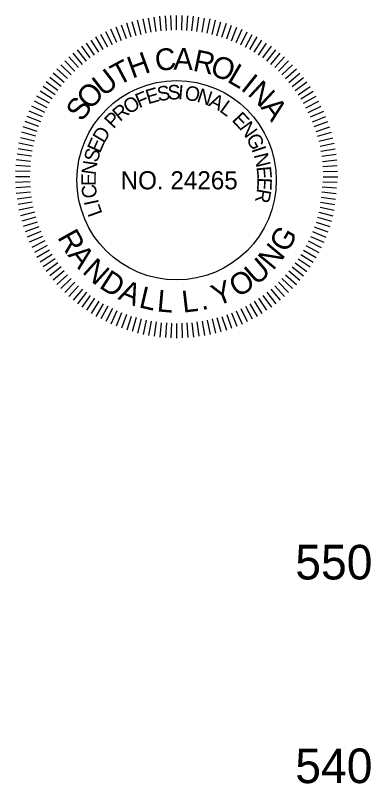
# Model space of a CAD drawing. Extents: x 1964849 to 1967422, y 1116563 to 1122210.
# Drawn here: x 1966503.4 to 1966590.7, y 1121475.5 to 1121664.1 of the extents above; entities that cross this region are included whole.
import ezdxf

# ---------------------------------------------------------------- set-up
doc = ezdxf.new("R2010")
doc.units = 0
doc.layers.add('RD_DDB_Profile_Elev', color=7, linetype='Continuous')
doc.layers.add('RD_TX_PEShield', color=7, linetype='Continuous')

msp = doc.modelspace()

# ---------------------------------------------------------------- linework, layer by layer
at = {"layer": 'RD_TX_PEShield'}
for p, q in [((1966539.21, 1121660.3), (1966538.84, 1121663.84)), ((1966539.21, 1121660.3), (1966538.84, 1121663.84)), ((1966540.47, 1121660.37), (1966540.22, 1121663.91)), ((1966540.47, 1121660.37), (1966540.22, 1121663.91)), ((1966541.72, 1121660.43), (1966541.6, 1121663.99)), ((1966541.72, 1121660.43), (1966541.6, 1121663.99)), ((1966542.98, 1121660.5), (1966542.98, 1121664.06)), ((1966542.98, 1121660.5), (1966542.98, 1121664.06)), ((1966544.24, 1121660.43), (1966544.36, 1121663.99)), ((1966544.24, 1121660.43), (1966544.36, 1121663.99)), ((1966545.49, 1121660.37), (1966545.74, 1121663.91)), ((1966545.49, 1121660.37), (1966545.74, 1121663.91)), ((1966546.75, 1121660.3), (1966547.12, 1121663.84)), ((1966546.75, 1121660.3), (1966547.12, 1121663.84)), ((1966531.84, 1121658.74), (1966530.74, 1121662.12)), ((1966531.84, 1121658.74), (1966530.74, 1121662.12)), ((1966533.06, 1121659.06), (1966532.08, 1121662.48)), ((1966533.06, 1121659.06), (1966532.08, 1121662.48)), ((1966534.27, 1121659.39), (1966533.41, 1121662.84)), ((1966534.27, 1121659.39), (1966533.41, 1121662.84)), ((1966535.49, 1121659.71), (1966534.75, 1121663.19)), ((1966535.49, 1121659.71), (1966534.75, 1121663.19)), ((1966536.73, 1121659.91), (1966536.11, 1121663.41)), ((1966536.73, 1121659.91), (1966536.11, 1121663.41)), ((1966537.97, 1121660.11), (1966537.48, 1121663.63)), ((1966537.97, 1121660.11), (1966537.48, 1121663.63)), ((1966547.99, 1121660.11), (1966548.49, 1121663.63)), ((1966547.99, 1121660.11), (1966548.49, 1121663.63)), ((1966549.23, 1121659.91), (1966549.85, 1121663.41)), ((1966549.23, 1121659.91), (1966549.85, 1121663.41)), ((1966550.48, 1121659.71), (1966551.22, 1121663.19)), ((1966550.48, 1121659.71), (1966551.22, 1121663.19)), ((1966550.48, 1121659.71), (1966551.22, 1121663.19)), ((1966551.69, 1121659.39), (1966552.55, 1121662.84)), ((1966551.69, 1121659.39), (1966552.55, 1121662.84)), ((1966551.69, 1121659.39), (1966552.55, 1121662.84)), ((1966552.9, 1121659.06), (1966553.88, 1121662.48)), ((1966552.9, 1121659.06), (1966553.88, 1121662.48)), ((1966552.9, 1121659.06), (1966553.88, 1121662.48)), ((1966554.12, 1121658.74), (1966555.22, 1121662.12)), ((1966554.12, 1121658.74), (1966555.22, 1121662.12)), ((1966554.12, 1121658.74), (1966555.22, 1121662.12)), ((1966528.32, 1121657.38), (1966526.87, 1121660.64)), ((1966528.32, 1121657.38), (1966526.87, 1121660.64)), ((1966529.49, 1121657.83), (1966528.16, 1121661.13)), ((1966529.49, 1121657.83), (1966528.16, 1121661.13)), ((1966530.67, 1121658.28), (1966529.45, 1121661.63)), ((1966530.67, 1121658.28), (1966529.45, 1121661.63)), ((1966555.29, 1121658.28), (1966556.51, 1121661.63)), ((1966555.29, 1121658.28), (1966556.51, 1121661.63)), ((1966555.29, 1121658.28), (1966556.51, 1121661.63)), ((1966556.47, 1121657.83), (1966557.8, 1121661.13)), ((1966556.47, 1121657.83), (1966557.8, 1121661.13)), ((1966556.47, 1121657.83), (1966557.8, 1121661.13)), ((1966557.64, 1121657.38), (1966559.09, 1121660.64)), ((1966557.64, 1121657.38), (1966559.09, 1121660.64)), ((1966557.64, 1121657.38), (1966559.09, 1121660.64)), ((1966524.96, 1121655.67), (1966523.18, 1121658.75)), ((1966524.96, 1121655.67), (1966523.18, 1121658.75)), ((1966526.08, 1121656.24), (1966524.41, 1121659.38)), ((1966526.08, 1121656.24), (1966524.41, 1121659.38)), ((1966527.2, 1121656.81), (1966525.64, 1121660.01)), ((1966527.2, 1121656.81), (1966525.64, 1121660.01)), ((1966558.76, 1121656.81), (1966560.32, 1121660.01)), ((1966558.76, 1121656.81), (1966560.32, 1121660.01)), ((1966558.76, 1121656.81), (1966560.32, 1121660.01)), ((1966559.88, 1121656.24), (1966561.55, 1121659.38)), ((1966559.88, 1121656.24), (1966561.55, 1121659.38)), ((1966559.88, 1121656.24), (1966561.55, 1121659.38)), ((1966561, 1121655.67), (1966562.78, 1121658.75)), ((1966561, 1121655.67), (1966562.78, 1121658.75)), ((1966561, 1121655.67), (1966562.78, 1121658.75)), ((1966521.79, 1121653.62), (1966519.7, 1121656.5)), ((1966521.79, 1121653.62), (1966519.7, 1121656.5)), ((1966522.85, 1121654.3), (1966520.86, 1121657.25)), ((1966522.85, 1121654.3), (1966520.86, 1121657.25)), ((1966523.9, 1121654.99), (1966522.02, 1121658)), ((1966523.9, 1121654.99), (1966522.02, 1121658)), ((1966562.06, 1121654.99), (1966563.94, 1121658)), ((1966562.06, 1121654.99), (1966563.94, 1121658)), ((1966562.06, 1121654.99), (1966563.94, 1121658)), ((1966563.11, 1121654.3), (1966565.1, 1121657.25)), ((1966563.11, 1121654.3), (1966565.1, 1121657.25)), ((1966563.11, 1121654.3), (1966565.1, 1121657.25)), ((1966564.17, 1121653.62), (1966566.26, 1121656.5)), ((1966564.17, 1121653.62), (1966566.26, 1121656.5)), ((1966564.17, 1121653.62), (1966566.26, 1121656.5)), ((1966519.84, 1121652.03), (1966517.55, 1121654.76)), ((1966519.84, 1121652.03), (1966517.55, 1121654.76)), ((1966520.82, 1121652.82), (1966518.63, 1121655.63)), ((1966520.82, 1121652.82), (1966518.63, 1121655.63)), ((1966565.15, 1121652.82), (1966567.33, 1121655.63)), ((1966565.15, 1121652.82), (1966567.33, 1121655.63)), ((1966565.15, 1121652.82), (1966567.33, 1121655.63)), ((1966566.12, 1121652.03), (1966568.41, 1121654.76)), ((1966566.12, 1121652.03), (1966568.41, 1121654.76)), ((1966566.12, 1121652.03), (1966568.41, 1121654.76)), ((1966517.97, 1121650.35), (1966515.5, 1121652.91)), ((1966517.97, 1121650.35), (1966515.5, 1121652.91)), ((1966518.86, 1121651.24), (1966516.48, 1121653.89)), ((1966518.86, 1121651.24), (1966516.48, 1121653.89)), ((1966567.1, 1121651.24), (1966569.48, 1121653.89)), ((1966567.1, 1121651.24), (1966569.48, 1121653.89)), ((1966567.1, 1121651.24), (1966569.48, 1121653.89)), ((1966567.99, 1121650.35), (1966570.46, 1121652.91)), ((1966567.99, 1121650.35), (1966570.46, 1121652.91)), ((1966567.99, 1121650.35), (1966570.46, 1121652.91)), ((1966516.19, 1121648.57), (1966513.55, 1121650.96)), ((1966516.19, 1121648.57), (1966513.55, 1121650.96)), ((1966517.08, 1121649.46), (1966514.53, 1121651.93)), ((1966517.08, 1121649.46), (1966514.53, 1121651.93)), ((1966568.88, 1121649.46), (1966571.44, 1121651.93)), ((1966568.88, 1121649.46), (1966571.44, 1121651.93)), ((1966568.88, 1121649.46), (1966571.44, 1121651.93)), ((1966569.77, 1121648.57), (1966572.41, 1121650.96)), ((1966569.77, 1121648.57), (1966572.41, 1121650.96)), ((1966569.77, 1121648.57), (1966572.41, 1121650.96)), ((1966514.61, 1121646.62), (1966511.81, 1121648.81)), ((1966514.61, 1121646.62), (1966511.81, 1121648.81)), ((1966515.4, 1121647.6), (1966512.68, 1121649.88)), ((1966515.4, 1121647.6), (1966512.68, 1121649.88)), ((1966570.56, 1121647.6), (1966573.28, 1121649.88)), ((1966570.56, 1121647.6), (1966573.28, 1121649.88)), ((1966570.56, 1121647.6), (1966573.28, 1121649.88)), ((1966571.35, 1121646.62), (1966574.15, 1121648.81)), ((1966571.35, 1121646.62), (1966574.15, 1121648.81)), ((1966571.35, 1121646.62), (1966574.15, 1121648.81)), ((1966513.82, 1121645.64), (1966510.94, 1121647.73)), ((1966513.82, 1121645.64), (1966510.94, 1121647.73)), ((1966572.14, 1121645.64), (1966575.02, 1121647.73)), ((1966572.14, 1121645.64), (1966575.02, 1121647.73)), ((1966572.14, 1121645.64), (1966575.02, 1121647.73)), ((1966512.45, 1121643.53), (1966509.44, 1121645.42)), ((1966512.45, 1121643.53), (1966509.44, 1121645.42)), ((1966513.13, 1121644.59), (1966510.19, 1121646.57)), ((1966513.13, 1121644.59), (1966510.19, 1121646.57)), ((1966572.83, 1121644.59), (1966575.78, 1121646.57)), ((1966572.83, 1121644.59), (1966575.78, 1121646.57)), ((1966572.83, 1121644.59), (1966575.78, 1121646.57)), ((1966573.51, 1121643.53), (1966576.53, 1121645.42)), ((1966573.51, 1121643.53), (1966576.53, 1121645.42)), ((1966573.51, 1121643.53), (1966576.53, 1121645.42)), ((1966511.77, 1121642.48), (1966508.68, 1121644.26)), ((1966511.77, 1121642.48), (1966508.68, 1121644.26)), ((1966574.2, 1121642.48), (1966577.28, 1121644.26)), ((1966574.2, 1121642.48), (1966577.28, 1121644.26)), ((1966574.2, 1121642.48), (1966577.28, 1121644.26)), ((1966510.62, 1121640.24), (1966507.43, 1121641.79)), ((1966510.62, 1121640.24), (1966507.43, 1121641.79)), ((1966511.19, 1121641.36), (1966508.05, 1121643.03)), ((1966511.19, 1121641.36), (1966508.05, 1121643.03)), ((1966574.77, 1121641.36), (1966577.91, 1121643.03)), ((1966574.77, 1121641.36), (1966577.91, 1121643.03)), ((1966574.77, 1121641.36), (1966577.91, 1121643.03)), ((1966575.34, 1121640.24), (1966578.53, 1121641.79)), ((1966575.34, 1121640.24), (1966578.53, 1121641.79)), ((1966575.34, 1121640.24), (1966578.53, 1121641.79)), ((1966510.05, 1121639.12), (1966506.8, 1121640.56)), ((1966510.05, 1121639.12), (1966506.8, 1121640.56)), ((1966575.91, 1121639.12), (1966579.16, 1121640.56)), ((1966575.91, 1121639.12), (1966579.16, 1121640.56)), ((1966575.91, 1121639.12), (1966579.16, 1121640.56)), ((1966509.15, 1121636.77), (1966505.81, 1121637.98)), ((1966509.15, 1121636.77), (1966505.81, 1121637.98)), ((1966509.6, 1121637.94), (1966506.3, 1121639.27)), ((1966509.6, 1121637.94), (1966506.3, 1121639.27)), ((1966576.36, 1121637.94), (1966579.66, 1121639.27)), ((1966576.36, 1121637.94), (1966579.66, 1121639.27)), ((1966576.36, 1121637.94), (1966579.66, 1121639.27)), ((1966576.81, 1121636.77), (1966580.15, 1121637.98)), ((1966576.81, 1121636.77), (1966580.15, 1121637.98)), ((1966576.81, 1121636.77), (1966580.15, 1121637.98)), ((1966508.7, 1121635.59), (1966505.31, 1121636.69)), ((1966508.7, 1121635.59), (1966505.31, 1121636.69)), ((1966577.26, 1121635.59), (1966580.65, 1121636.69)), ((1966577.26, 1121635.59), (1966580.65, 1121636.69)), ((1966577.26, 1121635.59), (1966580.65, 1121636.69)), ((1966508.05, 1121633.16), (1966504.6, 1121634.02)), ((1966508.05, 1121633.16), (1966504.6, 1121634.02)), ((1966508.37, 1121634.38), (1966504.96, 1121635.36)), ((1966508.37, 1121634.38), (1966504.96, 1121635.36)), ((1966577.59, 1121634.38), (1966581.01, 1121635.36)), ((1966577.59, 1121634.38), (1966581.01, 1121635.36)), ((1966577.59, 1121634.38), (1966581.01, 1121635.36)), ((1966577.91, 1121633.16), (1966581.36, 1121634.02)), ((1966577.91, 1121633.16), (1966581.36, 1121634.02)), ((1966577.91, 1121633.16), (1966581.36, 1121634.02)), ((1966507.72, 1121631.95), (1966504.24, 1121632.69)), ((1966507.72, 1121631.95), (1966504.24, 1121632.69)), ((1966578.24, 1121631.95), (1966581.72, 1121632.69)), ((1966578.24, 1121631.95), (1966581.72, 1121632.69)), ((1966578.24, 1121631.95), (1966581.72, 1121632.69)), ((1966507.33, 1121629.46), (1966503.81, 1121629.96)), ((1966507.33, 1121629.46), (1966503.81, 1121629.96)), ((1966507.53, 1121630.71), (1966504.03, 1121631.32)), ((1966507.53, 1121630.71), (1966504.03, 1121631.32)), ((1966578.44, 1121630.71), (1966581.94, 1121631.32)), ((1966578.44, 1121630.71), (1966581.94, 1121631.32)), ((1966578.44, 1121630.71), (1966581.94, 1121631.32)), ((1966578.63, 1121629.46), (1966582.15, 1121629.96)), ((1966578.63, 1121629.46), (1966582.15, 1121629.96)), ((1966578.63, 1121629.46), (1966582.15, 1121629.96)), ((1966507.13, 1121628.22), (1966503.59, 1121628.59)), ((1966507.13, 1121628.22), (1966503.59, 1121628.59)), ((1966578.83, 1121628.22), (1966582.37, 1121628.59)), ((1966578.83, 1121628.22), (1966582.37, 1121628.59)), ((1966578.83, 1121628.22), (1966582.37, 1121628.59)), ((1966507.07, 1121626.97), (1966503.52, 1121627.21)), ((1966507.07, 1121626.97), (1966503.52, 1121627.21)), ((1966578.89, 1121626.97), (1966582.44, 1121627.21)), ((1966578.89, 1121626.97), (1966582.44, 1121627.21)), ((1966578.89, 1121626.97), (1966582.44, 1121627.21)), ((1966506.94, 1121624.45), (1966503.38, 1121624.45)), ((1966506.94, 1121624.45), (1966503.38, 1121624.45)), ((1966507, 1121625.71), (1966503.45, 1121625.83)), ((1966507, 1121625.71), (1966503.45, 1121625.83)), ((1966578.96, 1121625.71), (1966582.51, 1121625.83)), ((1966578.96, 1121625.71), (1966582.51, 1121625.83)), ((1966578.96, 1121625.71), (1966582.51, 1121625.83)), ((1966579.03, 1121624.45), (1966582.59, 1121624.45)), ((1966579.03, 1121624.45), (1966582.59, 1121624.45)), ((1966579.03, 1121624.45), (1966582.59, 1121624.45)), ((1966507, 1121623.2), (1966503.45, 1121623.07)), ((1966507, 1121623.2), (1966503.45, 1121623.07)), ((1966578.89, 1121623.2), (1966582.44, 1121623.08)), ((1966578.89, 1121623.2), (1966582.44, 1121623.08)), ((1966507.07, 1121621.94), (1966503.52, 1121621.7)), ((1966507.07, 1121621.94), (1966503.52, 1121621.7)), ((1966507.13, 1121620.69), (1966503.59, 1121620.31)), ((1966507.13, 1121620.69), (1966503.59, 1121620.31)), ((1966578.63, 1121620.71), (1966582.15, 1121620.34)), ((1966578.63, 1121620.71), (1966582.15, 1121620.34)), ((1966578.76, 1121621.95), (1966582.3, 1121621.71)), ((1966578.76, 1121621.95), (1966582.3, 1121621.71)), ((1966507.33, 1121619.44), (1966503.81, 1121618.95)), ((1966507.33, 1121619.44), (1966503.81, 1121618.95)), ((1966578.5, 1121619.46), (1966582.01, 1121618.97)), ((1966578.5, 1121619.46), (1966582.01, 1121618.97)), ((1966507.53, 1121618.2), (1966504.03, 1121617.59)), ((1966507.53, 1121618.2), (1966504.03, 1121617.59)), ((1966507.72, 1121616.96), (1966504.24, 1121616.22)), ((1966507.72, 1121616.96), (1966504.24, 1121616.22)), ((1966578.24, 1121616.96), (1966581.72, 1121616.22)), ((1966578.24, 1121616.96), (1966581.72, 1121616.22)), ((1966578.37, 1121618.21), (1966581.87, 1121617.6)), ((1966578.37, 1121618.21), (1966581.87, 1121617.6)), ((1966508.05, 1121615.75), (1966504.6, 1121614.88)), ((1966508.05, 1121615.75), (1966504.6, 1121614.88)), ((1966577.91, 1121615.75), (1966581.36, 1121614.88)), ((1966577.91, 1121615.75), (1966581.36, 1121614.88)), ((1966508.37, 1121614.53), (1966504.96, 1121613.55)), ((1966508.37, 1121614.53), (1966504.96, 1121613.55)), ((1966508.7, 1121613.32), (1966505.31, 1121612.22)), ((1966577.26, 1121613.32), (1966580.65, 1121612.22)), ((1966577.26, 1121613.32), (1966580.65, 1121612.22)), ((1966577.59, 1121614.53), (1966581.01, 1121613.55)), ((1966577.59, 1121614.53), (1966581.01, 1121613.55)), ((1966509.15, 1121612.14), (1966505.81, 1121610.93)), ((1966509.15, 1121612.14), (1966505.81, 1121610.93)), ((1966576.81, 1121612.14), (1966580.15, 1121610.93)), ((1966576.81, 1121612.14), (1966580.15, 1121610.93)), ((1966509.6, 1121610.97), (1966506.3, 1121609.64)), ((1966509.6, 1121610.97), (1966506.3, 1121609.64)), ((1966510.05, 1121609.79), (1966506.8, 1121608.35)), ((1966510.05, 1121609.79), (1966506.8, 1121608.35)), ((1966575.91, 1121609.79), (1966579.16, 1121608.35)), ((1966575.91, 1121609.79), (1966579.16, 1121608.35)), ((1966576.36, 1121610.97), (1966579.66, 1121609.64)), ((1966576.36, 1121610.97), (1966579.66, 1121609.64)), ((1966510.62, 1121608.67), (1966507.43, 1121607.11)), ((1966510.62, 1121608.67), (1966507.43, 1121607.11)), ((1966511.19, 1121607.55), (1966508.05, 1121605.88)), ((1966511.19, 1121607.55), (1966508.05, 1121605.88)), ((1966574.77, 1121607.55), (1966577.91, 1121605.88)), ((1966574.77, 1121607.55), (1966577.91, 1121605.88)), ((1966575.34, 1121608.67), (1966578.53, 1121607.11)), ((1966575.34, 1121608.67), (1966578.53, 1121607.11)), ((1966511.77, 1121606.43), (1966508.68, 1121604.65)), ((1966511.77, 1121606.43), (1966508.68, 1121604.65)), ((1966512.45, 1121605.38), (1966509.44, 1121603.49)), ((1966512.45, 1121605.38), (1966509.44, 1121603.49)), ((1966573.51, 1121605.38), (1966576.53, 1121603.49)), ((1966573.51, 1121605.38), (1966576.53, 1121603.49)), ((1966574.2, 1121606.43), (1966577.28, 1121604.65)), ((1966574.2, 1121606.43), (1966577.28, 1121604.65)), ((1966513.13, 1121604.32), (1966510.19, 1121602.33)), ((1966513.13, 1121604.32), (1966510.19, 1121602.33)), ((1966572.83, 1121604.32), (1966575.78, 1121602.33)), ((1966572.83, 1121604.32), (1966575.78, 1121602.33)), ((1966513.82, 1121603.27), (1966510.94, 1121601.18)), ((1966513.82, 1121603.27), (1966510.94, 1121601.18)), ((1966514.61, 1121602.29), (1966511.81, 1121600.1)), ((1966514.61, 1121602.29), (1966511.81, 1121600.1)), ((1966571.35, 1121602.29), (1966574.15, 1121600.1)), ((1966571.35, 1121602.29), (1966574.15, 1121600.1)), ((1966572.14, 1121603.27), (1966575.02, 1121601.18)), ((1966572.14, 1121603.27), (1966575.02, 1121601.18)), ((1966515.4, 1121601.31), (1966512.68, 1121599.03)), ((1966515.4, 1121601.31), (1966512.68, 1121599.03)), ((1966516.19, 1121600.34), (1966513.55, 1121597.95)), ((1966516.19, 1121600.34), (1966513.55, 1121597.95)), ((1966569.77, 1121600.34), (1966572.41, 1121597.95)), ((1966569.77, 1121600.34), (1966572.41, 1121597.95)), ((1966570.56, 1121601.31), (1966573.28, 1121599.03)), ((1966570.56, 1121601.31), (1966573.28, 1121599.03)), ((1966517.08, 1121599.45), (1966514.53, 1121596.98)), ((1966517.08, 1121599.45), (1966514.53, 1121596.98)), ((1966517.97, 1121598.56), (1966515.5, 1121596)), ((1966517.97, 1121598.56), (1966515.5, 1121596)), ((1966567.99, 1121598.56), (1966570.46, 1121596)), ((1966567.99, 1121598.56), (1966570.46, 1121596)), ((1966568.88, 1121599.45), (1966571.44, 1121596.98)), ((1966568.88, 1121599.45), (1966571.44, 1121596.98)), ((1966518.86, 1121597.67), (1966516.48, 1121595.02)), ((1966518.86, 1121597.67), (1966516.48, 1121595.02)), ((1966519.84, 1121596.88), (1966517.55, 1121594.15)), ((1966519.84, 1121596.88), (1966517.55, 1121594.15)), ((1966520.82, 1121596.09), (1966518.63, 1121593.28)), ((1966520.82, 1121596.09), (1966518.63, 1121593.28)), ((1966565.15, 1121596.09), (1966567.33, 1121593.28)), ((1966565.15, 1121596.09), (1966567.33, 1121593.28)), ((1966566.12, 1121596.88), (1966568.41, 1121594.15)), ((1966566.12, 1121596.88), (1966568.41, 1121594.15)), ((1966567.1, 1121597.67), (1966569.48, 1121595.02)), ((1966521.79, 1121595.29), (1966519.7, 1121592.41)), ((1966521.79, 1121595.29), (1966519.7, 1121592.41)), ((1966522.85, 1121594.61), (1966520.86, 1121591.66)), ((1966522.85, 1121594.61), (1966520.86, 1121591.66)), ((1966563.11, 1121594.61), (1966565.1, 1121591.66)), ((1966563.11, 1121594.61), (1966565.1, 1121591.66)), ((1966564.17, 1121595.29), (1966566.26, 1121592.41)), ((1966564.17, 1121595.29), (1966566.26, 1121592.41)), ((1966523.9, 1121593.92), (1966522.02, 1121590.91)), ((1966523.9, 1121593.92), (1966522.02, 1121590.91)), ((1966524.96, 1121593.24), (1966523.18, 1121590.16)), ((1966524.96, 1121593.24), (1966523.18, 1121590.16)), ((1966526.08, 1121592.67), (1966524.41, 1121589.53)), ((1966526.08, 1121592.67), (1966524.41, 1121589.53)), ((1966559.88, 1121592.67), (1966561.55, 1121589.53)), ((1966559.88, 1121592.67), (1966561.55, 1121589.53)), ((1966561, 1121593.24), (1966562.78, 1121590.16)), ((1966561, 1121593.24), (1966562.78, 1121590.16)), ((1966562.06, 1121593.92), (1966563.94, 1121590.91)), ((1966562.06, 1121593.92), (1966563.94, 1121590.91)), ((1966527.2, 1121592.1), (1966525.64, 1121588.9)), ((1966527.2, 1121592.1), (1966525.64, 1121588.9)), ((1966528.32, 1121591.53), (1966526.87, 1121588.27)), ((1966528.32, 1121591.53), (1966526.87, 1121588.27)), ((1966529.49, 1121591.07), (1966528.16, 1121587.78)), ((1966529.49, 1121591.07), (1966528.16, 1121587.78)), ((1966530.67, 1121590.62), (1966529.45, 1121587.28)), ((1966530.67, 1121590.62), (1966529.45, 1121587.28)), ((1966555.29, 1121590.62), (1966556.51, 1121587.28)), ((1966555.29, 1121590.62), (1966556.51, 1121587.28)), ((1966556.47, 1121591.07), (1966557.8, 1121587.78)), ((1966556.47, 1121591.07), (1966557.8, 1121587.78)), ((1966557.64, 1121591.53), (1966559.09, 1121588.27)), ((1966557.64, 1121591.53), (1966559.09, 1121588.27)), ((1966558.76, 1121592.1), (1966560.32, 1121588.9)), ((1966558.76, 1121592.1), (1966560.32, 1121588.9)), ((1966531.84, 1121590.17), (1966530.74, 1121586.79)), ((1966531.84, 1121590.17), (1966530.74, 1121586.79)), ((1966533.06, 1121589.85), (1966532.08, 1121586.43)), ((1966533.06, 1121589.85), (1966532.08, 1121586.43)), ((1966534.27, 1121589.52), (1966533.41, 1121586.07)), ((1966534.27, 1121589.52), (1966533.41, 1121586.07)), ((1966535.49, 1121589.2), (1966534.75, 1121585.71)), ((1966535.49, 1121589.2), (1966534.75, 1121585.71)), ((1966536.73, 1121589), (1966536.11, 1121585.5)), ((1966536.73, 1121589), (1966536.11, 1121585.5)), ((1966537.97, 1121588.8), (1966537.48, 1121585.28)), ((1966537.97, 1121588.8), (1966537.48, 1121585.28)), ((1966539.21, 1121588.61), (1966538.84, 1121585.07)), ((1966539.21, 1121588.61), (1966538.84, 1121585.07)), ((1966540.47, 1121588.54), (1966540.22, 1121584.99)), ((1966540.47, 1121588.54), (1966540.22, 1121584.99)), ((1966541.72, 1121588.48), (1966541.6, 1121584.92)), ((1966541.72, 1121588.48), (1966541.6, 1121584.92)), ((1966542.98, 1121588.41), (1966542.98, 1121584.85)), ((1966542.98, 1121588.41), (1966542.98, 1121584.85)), ((1966544.24, 1121588.48), (1966544.36, 1121584.92)), ((1966544.24, 1121588.48), (1966544.36, 1121584.92)), ((1966545.49, 1121588.54), (1966545.74, 1121584.99)), ((1966545.49, 1121588.54), (1966545.74, 1121584.99)), ((1966546.75, 1121588.61), (1966547.12, 1121585.07)), ((1966546.75, 1121588.61), (1966547.12, 1121585.07)), ((1966547.99, 1121588.8), (1966548.49, 1121585.28)), ((1966547.99, 1121588.8), (1966548.49, 1121585.28)), ((1966549.23, 1121589), (1966549.85, 1121585.5)), ((1966549.23, 1121589), (1966549.85, 1121585.5)), ((1966550.48, 1121589.2), (1966551.22, 1121585.71)), ((1966550.48, 1121589.2), (1966551.22, 1121585.71)), ((1966551.69, 1121589.52), (1966552.55, 1121586.07)), ((1966551.69, 1121589.52), (1966552.55, 1121586.07)), ((1966552.9, 1121589.85), (1966553.88, 1121586.43)), ((1966552.9, 1121589.85), (1966553.88, 1121586.43)), ((1966554.12, 1121590.17), (1966555.22, 1121586.79)), ((1966554.12, 1121590.17), (1966555.22, 1121586.79))]:
    msp.add_line(p, q, dxfattribs=at)
msp.add_circle((1966542.98, 1121623.58), 24.48, dxfattribs=at)

# ---------------------------------------------------------------- texts
at = {"layer": 'RD_DDB_Profile_Elev'}
for s, p in [('550', (1966572.14, 1121525.58)), ('540', (1966572.14, 1121475.58))]:
    msp.add_text(s, height=8.5, dxfattribs=at).set_placement(p)
at = {"layer": 'RD_TX_PEShield'}
for s, height, rotation, p in [('H', 5.34, 19.9102, (1966532.08, 1121648.5)), ('C', 5.34, 6.8832, (1966537.98, 1121650.31)), ('A', 5.34, 357.9448, (1966542.19, 1121650.77)), ('R', 5.34, 348.267, (1966546.77, 1121650.51)), ('T', 5.34, 28.0947, (1966528.64, 1121646.69)), ('O', 5.34, 339.3286, (1966550.91, 1121649.6)), ('U', 5.34, 37.7726, (1966524.96, 1121643.95)), ('L', 5.34, 329.6507, (1966555.17, 1121647.89)), ('I', 5.34, 321.4663, (1966558.51, 1121645.91)), ('O', 5.34, 47.4504, (1966521.79, 1121640.63)), ('S', 3.56, 8.6909, (1966538.47, 1121642.96)), ('S', 3.56, 1.79, (1966540.83, 1121643.37)), ('I', 3.56, 354.889, (1966543.22, 1121643.48)), ('N', 5.34, 317.0007, (1966560.2, 1121644.63)), ('F', 3.56, 23.0853, (1966533.79, 1121641.23)), ('E', 3.56, 16.1843, (1966535.98, 1121642.21)), ('O', 3.56, 350.4045, (1966544.78, 1121643.4)), ('N', 3.56, 341.7029, (1966547.76, 1121642.9)), ('S', 5.34, 54.9027, (1966519.76, 1121637.74)), ('O', 3.56, 31.7869, (1966531.23, 1121639.64)), ('A', 3.56, 333.0013, (1966550.63, 1121641.96)), ('L', 3.56, 324.2997, (1966553.32, 1121640.59)), ('R', 3.56, 39.8902, (1966529.08, 1121637.82)), ('A', 5.34, 307.3229, (1966563.5, 1121641.44)), ('P', 3.56, 46.7912, (1966527.47, 1121636.05)), ('E', 3.56, 313.2251, (1966556.39, 1121638.28)), ('N', 3.56, 305.7317, (1966558.2, 1121636.41)), ('D', 3.56, 59.074, (1966525.17, 1121632.46)), ('E', 3.56, 66.5674, (1966524.16, 1121630.06)), ('G', 3.56, 297.0301, (1966559.96, 1121633.96)), ('I', 3.56, 288.3285, (1966561.34, 1121631.27)), ('S', 3.56, 73.4683, (1966523.52, 1121627.76)), ('N', 3.56, 283.8441, (1966561.89, 1121629.81)), ('N', 3.56, 82.17, (1966523.11, 1121624.76)), ('E', 3.56, 275.1424, (1966562.61, 1121626.88)), ('E', 3.56, 89.6633, (1966523.13, 1121622.16)), ('C', 3.56, 97.7667, (1966523.52, 1121619.38)), ('E', 3.56, 267.6491, (1966562.87, 1121624.29)), ('R', 3.56, 260.1557, (1966562.8, 1121621.69)), ('I', 3.56, 102.2511, (1966523.91, 1121617.87)), ('L', 3.56, 109.7445, (1966524.82, 1121615.43)), ('R', 5.34, 299.1493, (1966513.58, 1121609.6)), ('G', 5.34, 60.1113, (1966570.09, 1121605.55)), ('N', 5.34, 50.4335, (1966566.67, 1121601.25)), ('A', 5.34, 308.0877, (1966516.11, 1121605.2)), ('N', 5.34, 317.7655, (1966519.58, 1121600.95)), ('U', 5.34, 40.7556, (1966562.58, 1121597.59)), ('D', 5.34, 327.4433, (1966523.72, 1121597.34)), ('O', 5.34, 31.0778, (1966557.94, 1121594.66)), ('A', 5.34, 337.1212, (1966528.4, 1121594.47)), ('Y', 5.34, 21.4, (1966552.86, 1121592.56)), ('L', 5.34, 346.799, (1966533.5, 1121592.43)), ('L', 5.34, 354.9835, (1966538.03, 1121591.4)), ('L', 5.34, 6.5171, (1966544.56, 1121591.06)), ('.', 5.34, 14.7016, (1966549.18, 1121591.62))]:
    msp.add_text(s, height=height, rotation=rotation, dxfattribs=at).set_placement(p)
msp.add_text('NO. 24265', height=4.45, dxfattribs=at).set_placement((1966529.23, 1121621.35))

doc.saveas('drawing.dxf')
